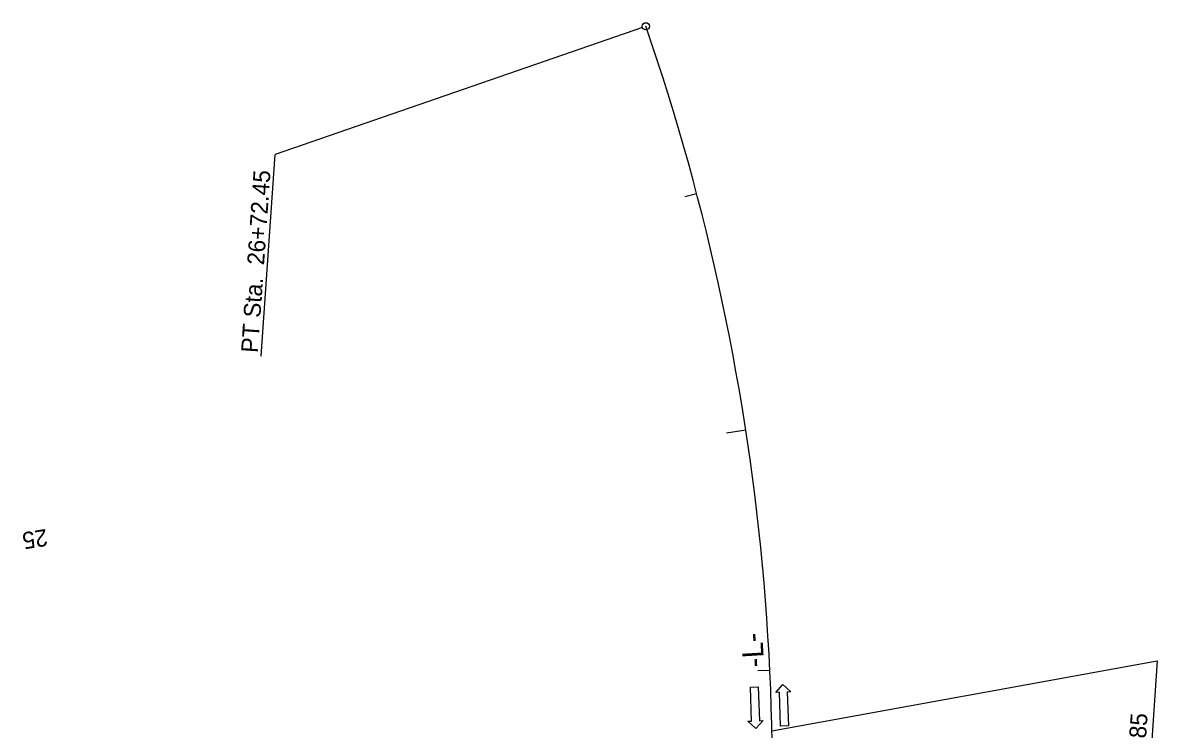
# Model space of a CAD drawing. Extents: x 2599146 to 2600072, y 728518 to 730269.
# Drawn here: x 2599222.2 to 2599691.6, y 729976.9 to 730269.4 of the extents above; entities that cross this region are included whole.
import ezdxf

# ---------------------------------------------------------------- set-up
doc = ezdxf.new("R2010")
doc.units = 0
for name, color, linetype in [('Old_Level_4', 7, 'Continuous'), ('Prop Horizontal Alignment', 7, 'Continuous'), ('Prop Horizontal Alignment Station Label', 7, 'Continuous'), ('Prop Horizontal Alignment Tick Label', 7, 'Continuous'), ('Prop Horizontal Alignment Tick Large', 7, 'Continuous'), ('Prop Horizontal Alignment Tick Small', 7, 'Continuous')]:
    doc.layers.add(name, color=color, linetype=linetype)

msp = doc.modelspace()

# ---------------------------------------------------------------- linework, layer by layer
at = {"layer": 'Old_Level_4'}
for p, q in [((2599523.23, 729994.32), (2599526.53, 729994.44)), ((2599523.74, 729980.33), (2599523.23, 729994.32)), ((2599526.53, 729994.44), (2599527.04, 729980.45)), ((2599533.72, 729992.15), (2599536.69, 729995.42)), ((2599535.22, 729992.21), (2599533.72, 729992.15)), ((2599535.76, 729978.22), (2599535.22, 729992.21)), ((2599536.69, 729995.42), (2599540.01, 729992.4)), ((2599540.01, 729992.4), (2599538.51, 729992.34)), ((2599538.51, 729992.34), (2599539.06, 729978.35)), ((2599522.24, 729980.27), (2599523.74, 729980.33)), ((2599525.56, 729977.24), (2599522.24, 729980.27)), ((2599528.54, 729980.5), (2599525.56, 729977.24)), ((2599527.04, 729980.45), (2599528.54, 729980.5)), ((2599539.06, 729978.35), (2599535.76, 729978.22))]:
    msp.add_line(p, q, dxfattribs=at)
at = {"layer": 'Prop Horizontal Alignment'}
msp.add_arc((2598577.38, 729955.9), 955, 350.73628, 19.06961, dxfattribs=at)
at = {"layer": 'Prop Horizontal Alignment Station Label'}
for p, q in [((2599478.55, 730267.42), (2599326.58, 730214.89)), ((2599320.81, 730131.34), (2599326.58, 730214.89)), ((2599532.16, 729976.3), (2599691.61, 730005.27)), ((2599691.61, 730005.27), (2599681.78, 729862.54))]:
    msp.add_line(p, q, dxfattribs=at)
msp.add_circle((2599479.97, 730267.91), 1.5, dxfattribs=at)
at = {"layer": 'Prop Horizontal Alignment Tick Large'}
msp.add_line((2599521.33, 730100.74), (2599513.42, 730099.53), dxfattribs=at)
at = {"layer": 'Prop Horizontal Alignment Tick Small'}
for p, q in [((2599501.02, 730198.61), (2599496.18, 730197.34)), ((2599531.3, 730001.28), (2599526.3, 730001.05))]:
    msp.add_line(p, q, dxfattribs=at)

# ---------------------------------------------------------------- texts
at = {"layer": 'Prop Horizontal Alignment Station Label'}
for s, height, rotation, p in [('PT Sta.  26+72.45', 7, 86.0374, (2599319.48, 730132.6)), ('-L-', 8.75, 93.4449, (2599528.99, 730002.77)), ('END TIP PROJECT B-4185', 7, 86.0601, (2599679.67, 729867.64))]:
    msp.add_text(s, height=height, rotation=rotation, dxfattribs=at).set_placement(p)
at = {"layer": 'Prop Horizontal Alignment Tick Label'}
msp.add_text('25', height=7, rotation=188.7236, dxfattribs=at).set_placement((2599231.88, 730059.87))

doc.saveas('drawing.dxf')
